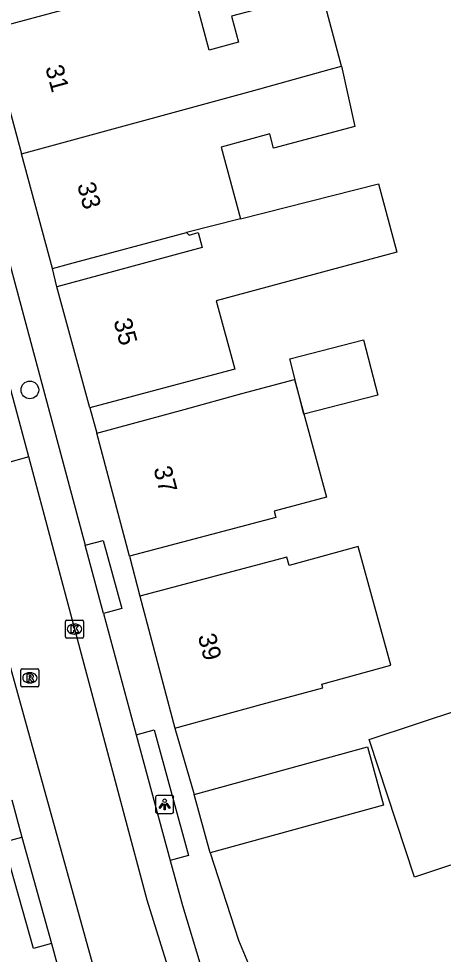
# Model space of a CAD drawing. Extents: x 159265 to 160143, y 383413 to 384319.
# Drawn here: x 159676.8 to 159700.3, y 383618.3 to 383670 of the extents above; entities that cross this region are included whole.
import ezdxf

# ---------------------------------------------------------------- set-up
doc = ezdxf.new("R2010")
doc.units = 0
for name, color, linetype in [('IMGEO_Boom', 7, 'Continuous'), ('IMGEO_Kolk', 7, 'Continuous'), ('IMGEO_Lichtpunt', 7, 'Continuous'), ('IMGEO_Pand', 7, 'Continuous'), ('IMGEO_Pand_nummerreeks', 7, 'Continuous'), ('IMGEO_Rijbaan_lokaal_open', 7, 'Continuous'), ('IMGEO_Rioolput', 7, 'Continuous'), ('IMGEO_Voetpad_open', 7, 'Continuous')]:
    doc.layers.add(name, color=color, linetype=linetype)

msp = doc.modelspace()

# ---------------------------------------------------------------- linework, layer by layer
at = {"layer": 'IMGEO_Boom'}
msp.add_circle((159677.423, 383649.48), 0.489, dxfattribs=at)
at = {"layer": 'IMGEO_Kolk'}
for p, q in [((159679.395, 383635.823), (159679.395, 383636.675)), ((159679.47, 383636.749), (159680.322, 383636.749)), ((159679.883, 383636.529), (159679.908, 383636.529)), ((159680.396, 383636.675), (159680.396, 383635.823)), ((159679.906, 383635.969), (159679.881, 383635.969)), ((159680.322, 383635.749), (159679.47, 383635.749))]:
    msp.add_line(p, q, dxfattribs=at)
for points in [[(159679.395, 383635.823), (159679.395, 383636.675)], [(159679.47, 383636.749), (159680.322, 383636.749)], [(159679.716, 383636.449), (159679.839, 383636.449), (159679.839, 383636.298), (159679.969, 383636.449), (159680.133, 383636.449), (159679.987, 383636.298), (159680.14, 383636.049), (159679.988, 383636.049), (159679.903, 383636.213), (159679.839, 383636.146), (159679.839, 383636.049), (159679.716, 383636.049), (159679.716, 383636.449)], [(159680.396, 383636.675), (159680.396, 383635.823)], [(159680.322, 383635.749), (159679.47, 383635.749)]]:
    msp.add_lwpolyline(points, dxfattribs=at)
for centre, start, end in [((159679.472, 383636.673), 91.552, 178.448), ((159679.472, 383636.673), 91.552, 178.448), ((159680.32, 383636.673), 1.552, 88.448), ((159680.32, 383636.673), 1.552, 88.448), ((159679.472, 383635.825), 181.552, 268.448), ((159679.472, 383635.825), 181.552, 268.448), ((159680.32, 383635.825), 271.552, 358.448), ((159680.32, 383635.825), 271.552, 358.448)]:
    msp.add_arc(centre, 0.0765, start, end, dxfattribs=at)
for centre, major_axis, ratio, start_param, end_param in [((159679.882, 383636.249), (-0.387, 0.002), 0.722429, 4.712389, 7.853982), ((159679.907, 383636.249), (-0.39, 0.002), 0.717154, 1.570796, 4.712389)]:
    msp.add_ellipse(centre, major_axis=major_axis, ratio=ratio, start_param=start_param, end_param=end_param, dxfattribs=at)
at = {"layer": 'IMGEO_Lichtpunt'}
for p, q in [((159684.386, 383626.953), (159684.386, 383626.146)), ((159684.386, 383626.953), (159684.386, 383626.146)), ((159685.288, 383627.048), (159684.48, 383627.048)), ((159685.288, 383627.048), (159684.48, 383627.048)), ((159685.382, 383626.146), (159685.382, 383626.953)), ((159685.382, 383626.146), (159685.382, 383626.953)), ((159684.48, 383626.052), (159685.288, 383626.052)), ((159684.48, 383626.052), (159685.288, 383626.052))]:
    msp.add_line(p, q, dxfattribs=at)
for points in [[(159684.76, 383626.617), (159684.799, 383626.589), (159684.611, 383626.327), (159684.573, 383626.354), (159684.76, 383626.617)], [(159684.972, 383626.589), (159685.01, 383626.616), (159685.197, 383626.354), (159685.158, 383626.326), (159684.972, 383626.589)], [(159684.862, 383626.569), (159684.909, 383626.569), (159684.909, 383626.247), (159684.862, 383626.247), (159684.862, 383626.569)]]:
    msp.add_lwpolyline(points, dxfattribs=at)
msp.add_circle((159684.885, 383626.751), 0.0994, dxfattribs=at)
for centre, start, end in [((159684.48, 383626.953), 90, 180), ((159684.48, 383626.953), 90, 180), ((159685.288, 383626.953), 0, 90), ((159685.288, 383626.953), 0, 90), ((159684.48, 383626.146), 180, 270), ((159684.48, 383626.146), 180, 270), ((159685.288, 383626.146), 270, 0), ((159685.288, 383626.146), 270, 360)]:
    msp.add_arc(centre, 0.0946, start, end, dxfattribs=at)
at = {"layer": 'IMGEO_Pand'}
for points in [[(159694.676, 383667.394), (159693.581, 383671.494), (159692.879, 383671.305), (159688.586, 383670.15), (159688.97, 383668.721), (159687.354, 383668.286), (159686.337, 383672.067), (159682.576, 383671.055), (159682.503, 383671.376), (159679.923, 383670.682), (159675.094, 383669.383)], [(159675.094, 383669.383), (159676.953, 383662.548)], [(159676.953, 383662.548), (159689.814, 383666.044), (159693.984, 383667.202), (159694.676, 383667.394)], [(159694.676, 383667.394), (159695.408, 383664.06), (159690.908, 383662.859), (159690.698, 383663.643), (159688.005, 383662.918), (159689.072, 383658.952)], [(159678.679, 383656.202), (159676.953, 383662.548)], [(159689.072, 383658.952), (159696.713, 383660.877), (159697.729, 383657.099), (159691.212, 383655.346), (159687.739, 383654.412), (159688.758, 383650.624), (159685.574, 383649.778), (159680.741, 383648.493)], [(159689.072, 383658.952), (159686.092, 383658.199)], [(159678.679, 383656.202), (159679.625, 383656.457), (159686.092, 383658.199)], [(159686.092, 383658.199), (159686.242, 383658.049), (159686.744, 383658.184), (159686.967, 383657.353), (159678.921, 383655.189)], [(159680.741, 383648.493), (159678.921, 383655.189)], [(159696.677, 383649.197), (159692.591, 383648.144), (159691.805, 383651.195), (159695.891, 383652.247), (159696.677, 383649.197)], [(159681.13, 383647.09), (159685.956, 383648.403), (159689.161, 383649.275), (159692.061, 383650.064), (159693.833, 383643.55), (159690.951, 383642.766), (159691.043, 383642.431), (159682.933, 383640.283)], [(159682.933, 383640.283), (159681.13, 383647.09)], [(159685.451, 383630.776), (159690.276, 383632.09), (159693.635, 383633.004), (159693.581, 383633.201), (159697.392, 383634.249), (159695.584, 383640.823), (159691.774, 383639.775), (159691.65, 383640.223), (159683.519, 383638.069)], [(159683.519, 383638.069), (159685.451, 383630.776)], [(159702.648, 383623.827), (159698.718, 383622.525), (159696.193, 383630.145), (159701.332, 383631.847), (159703.041, 383626.69)], [(159686.511, 383627.099), (159696.107, 383629.733), (159696.991, 383626.512), (159687.395, 383623.878)], [(159687.395, 383623.878), (159686.511, 383627.099)]]:
    msp.add_lwpolyline(points, dxfattribs=at)
at = {"layer": 'IMGEO_Rijbaan_lokaal_open'}
for points in [[(159677.362, 383645.771), (159675.226, 383653.663)], [(159677.362, 383645.771), (159673.428, 383644.681)], [(159691.977, 383598.671), (159685.312, 383616.758), (159683.923, 383621.261), (159677.362, 383645.771)], [(159688.04, 383597.458), (159681.837, 383614.368), (159673.428, 383644.681)]]:
    msp.add_lwpolyline(points, dxfattribs=at)
at = {"layer": 'IMGEO_Rioolput'}
for p, q in [((159676.926, 383633.127), (159676.926, 383633.979)), ((159677.001, 383634.053), (159677.853, 383634.053)), ((159677.927, 383633.979), (159677.927, 383633.127)), ((159677.414, 383633.833), (159677.439, 383633.833)), ((159677.853, 383633.053), (159677.001, 383633.053)), ((159677.437, 383633.273), (159677.412, 383633.273))]:
    msp.add_line(p, q, dxfattribs=at)
for points in [[(159676.926, 383633.127), (159676.926, 383633.979)], [(159677.001, 383634.053), (159677.853, 383634.053)], [(159677.927, 383633.979), (159677.927, 383633.127)], [(159677.515, 383633.751), (159677.263, 383633.753), (159677.263, 383633.353)], [(159677.263, 383633.353), (159677.387, 383633.353), (159677.387, 383633.515), (159677.398, 383633.515)], [(159677.441, 383633.672), (159677.387, 383633.672), (159677.387, 383633.591)], [(159677.387, 383633.591), (159677.439, 383633.591)], [(159677.445, 383633.486), (159677.516, 383633.353), (159677.656, 383633.353), (159677.591, 383633.479)], [(159677.853, 383633.053), (159677.001, 383633.053)]]:
    msp.add_lwpolyline(points, dxfattribs=at)
for centre, radius, start, end in [((159677.003, 383633.977), 0.0765, 91.552, 178.448), ((159677.003, 383633.977), 0.0765, 91.552, 178.448), ((159677.851, 383633.977), 0.0765, 1.552, 88.448), ((159677.851, 383633.977), 0.0765, 1.552, 88.448), ((159677.397, 383633.462), 0.0533, 26.0293, 88.6989), ((159677.423, 383633.78), 0.19, 274.7715, 282.9687), ((159677.447, 383633.576), 0.0964, 77.0061, 93.1865), ((159677.461, 383633.633), 0.0378, 276.6634, 79.6772), ((159677.514, 383633.641), 0.109, 350.3612, 89.416), ((159677.512, 383633.641), 0.112, 277.5842, 350.9817), ((159677.496, 383633.426), 0.108, 29.5134, 73.7905), ((159677.003, 383633.129), 0.0765, 181.552, 268.448), ((159677.003, 383633.129), 0.0765, 181.552, 268.448), ((159677.851, 383633.129), 0.0765, 271.552, 358.448), ((159677.851, 383633.129), 0.0765, 271.552, 358.448)]:
    msp.add_arc(centre, radius, start, end, dxfattribs=at)
for centre, major_axis, ratio, start_param, end_param in [((159677.413, 383633.553), (-0.387, 0.002), 0.722429, 4.712389, 7.853982), ((159677.438, 383633.553), (-0.39, 0.002), 0.717154, 1.570796, 4.712389)]:
    msp.add_ellipse(centre, major_axis=major_axis, ratio=ratio, start_param=start_param, end_param=end_param, dxfattribs=at)
at = {"layer": 'IMGEO_Voetpad_open'}
for points in [[(159670.837, 383676.812), (159680.482, 383640.885)], [(159678.921, 383655.189), (159678.679, 383656.202)], [(159680.741, 383648.493), (159681.13, 383647.09)], [(159680.482, 383640.885), (159681.486, 383641.157), (159682.509, 383637.383), (159681.505, 383637.111)], [(159681.505, 383637.111), (159680.482, 383640.885)], [(159682.933, 383640.283), (159683.519, 383638.069)], [(159681.505, 383637.111), (159683.304, 383630.406)], [(159685.451, 383630.776), (159686.511, 383627.099)], [(159683.304, 383630.406), (159684.308, 383630.679), (159686.199, 383623.726), (159685.195, 383623.453)], [(159683.304, 383630.406), (159685.195, 383623.453)], [(159676.427, 383626.797), (159676.974, 383624.745)], [(159678.621, 383618.855), (159677.619, 383618.575), (159675.972, 383624.465), (159676.974, 383624.745)], [(159676.974, 383624.745), (159678.621, 383618.855)], [(159687.395, 383623.878), (159688.975, 383619.041), (159690.437, 383615.491)], [(159685.195, 383623.453), (159685.869, 383620.959), (159686.892, 383617.599)], [(159678.621, 383618.855), (159679.265, 383616.478), (159679.683, 383615.1), (159680.209, 383613.64), (159685.394, 383599.482)]]:
    msp.add_lwpolyline(points, dxfattribs=at)

# ---------------------------------------------------------------- texts
at = {"layer": 'IMGEO_Pand_nummerreeks'}
for s, rotation, p in [('31', 285.2175, (159678.268, 383667.315)), ('33', 285.2175, (159680.032, 383660.831)), ('35', 285.2059, (159682.045, 383653.3)), ('37', 284.8337, (159684.256, 383645.13)), ('39', 284.8394, (159686.709, 383635.866))]:
    msp.add_text(s, height=1, rotation=rotation, dxfattribs=at).set_placement(p)

doc.saveas('drawing.dxf')
